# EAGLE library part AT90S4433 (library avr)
MICROCONTROLLER 4 Kbytes FLASH 128 bytes SRAM 256 bytes EEPROM UART 6-channel 10 bit ADC
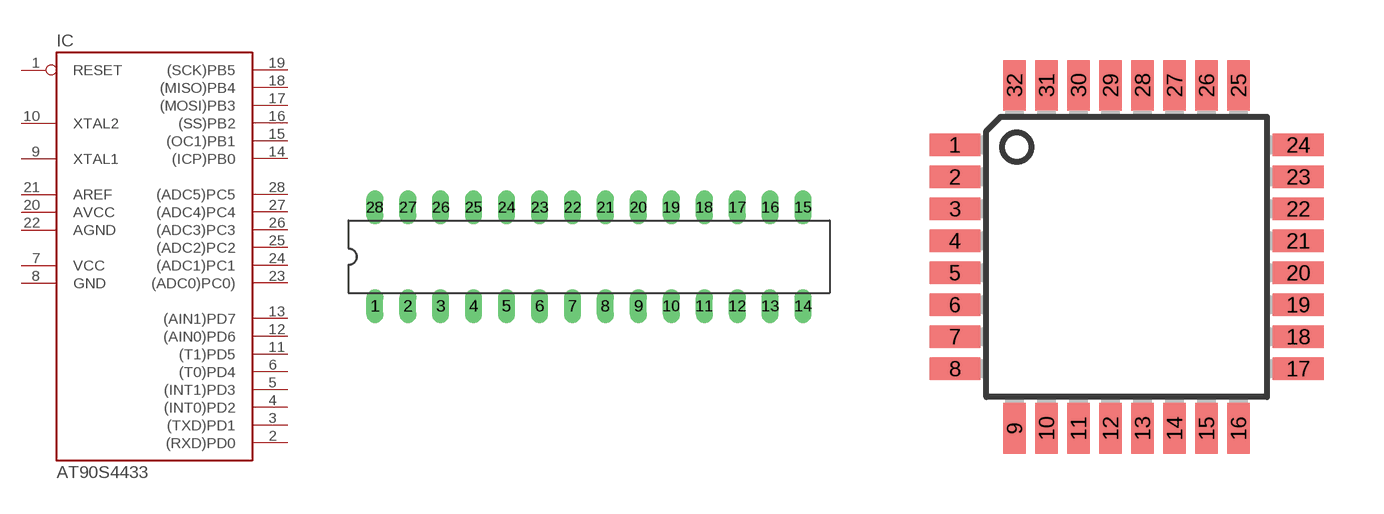
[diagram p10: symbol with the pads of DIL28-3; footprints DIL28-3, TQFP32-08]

Designator prefix IC

## AT90S4433P  [DIL28-3]
1  RESET  in
2  (RXD)PD0
3  (TXD)PD1
4  (INT0)PD2
5  (INT1)PD3
6  (T0)PD4
7  VCC  pwr
8  GND  pwr
9  XTAL1
10  XTAL2
11  (T1)PD5
12  (AIN0)PD6
13  (AIN1)PD7
14  (ICP)PB0
15  (OC1)PB1
16  (SS)PB2
17  (MOSI)PB3
18  (MISO)PB4
19  (SCK)PB5
20  AVCC  pwr
21  AREF  pwr
22  AGND  pwr
23  (ADC0)PC0)
24  (ADC1)PC1
25  (ADC2)PC2
26  (ADC3)PC3
27  (ADC4)PC4
28  (ADC5)PC5

## AT90S4433A  [TQFP32-08]
1  (INT1)PD3
2  (T0)PD4
4  VCC  pwr
5  GND  pwr
7  XTAL1
8  XTAL2
9  (T1)PD5
10  (AIN0)PD6
11  (AIN1)PD7
12  (ICP)PB0
13  (OC1)PB1
14  (SS)PB2
15  (MOSI)PB3
16  (MISO)PB4
17  (SCK)PB5
18  AVCC  pwr
20  AREF  pwr
21  AGND  pwr
23  (ADC0)PC0)
24  (ADC1)PC1
25  (ADC2)PC2
26  (ADC3)PC3
27  (ADC4)PC4
28  (ADC5)PC5
29  RESET  in
30  (RXD)PD0
31  (TXD)PD1
32  (INT0)PD2

## Footprint DIL28-3 (pad centres in mm)
Dual In Line 0.3 inch
drill 0.813 long: 1 -16.51,-3.81; 2 -13.97,-3.81; 3 -11.43,-3.81; 4 -8.89,-3.81; 5 -6.35,-3.81; 6 -3.81,-3.81; 7 -1.27,-3.81; 8 1.27,-3.81; 9 3.81,-3.81; 10 6.35,-3.81; 11 8.89,-3.81; 12 11.43,-3.81; 13 13.97,-3.81; 14 16.51,-3.81; 15 16.51,3.81; 16 13.97,3.81; 17 11.43,3.81; 18 8.89,3.81; 19 6.35,3.81; 20 3.81,3.81; 21 1.27,3.81; 22 -1.27,3.81; 23 -3.81,3.81; 24 -6.35,3.81; 25 -8.89,3.81; 26 -11.43,3.81; 27 -13.97,3.81; 28 -16.51,3.81

## Footprint TQFP32-08 (pad centres in mm)
Thin Plasic Quad Flat Package Grid 0.8 mm
smd 1.27 x 0.559: 1 -4.293,2.8; 2 -4.293,2; 3 -4.293,1.2; 4 -4.293,0.4; 5 -4.293,-0.4; 6 -4.293,-1.2; 7 -4.293,-2; 8 -4.293,-2.8; 17 4.293,-2.8; 18 4.293,-2; 19 4.293,-1.2; 20 4.293,-0.4; 21 4.293,0.4; 22 4.293,1.2; 23 4.293,2; 24 4.293,2.8
smd 0.559 x 1.27: 9 -2.8,-4.293; 10 -2,-4.293; 11 -1.2,-4.293; 12 -0.4,-4.293; 13 0.4,-4.293; 14 1.2,-4.293; 15 2,-4.293; 16 2.8,-4.293; 25 2.8,4.293; 26 2,4.293; 27 1.2,4.293; 28 0.4,4.293; 29 -0.4,4.293; 30 -1.2,4.293; 31 -2,4.293; 32 -2.8,4.293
